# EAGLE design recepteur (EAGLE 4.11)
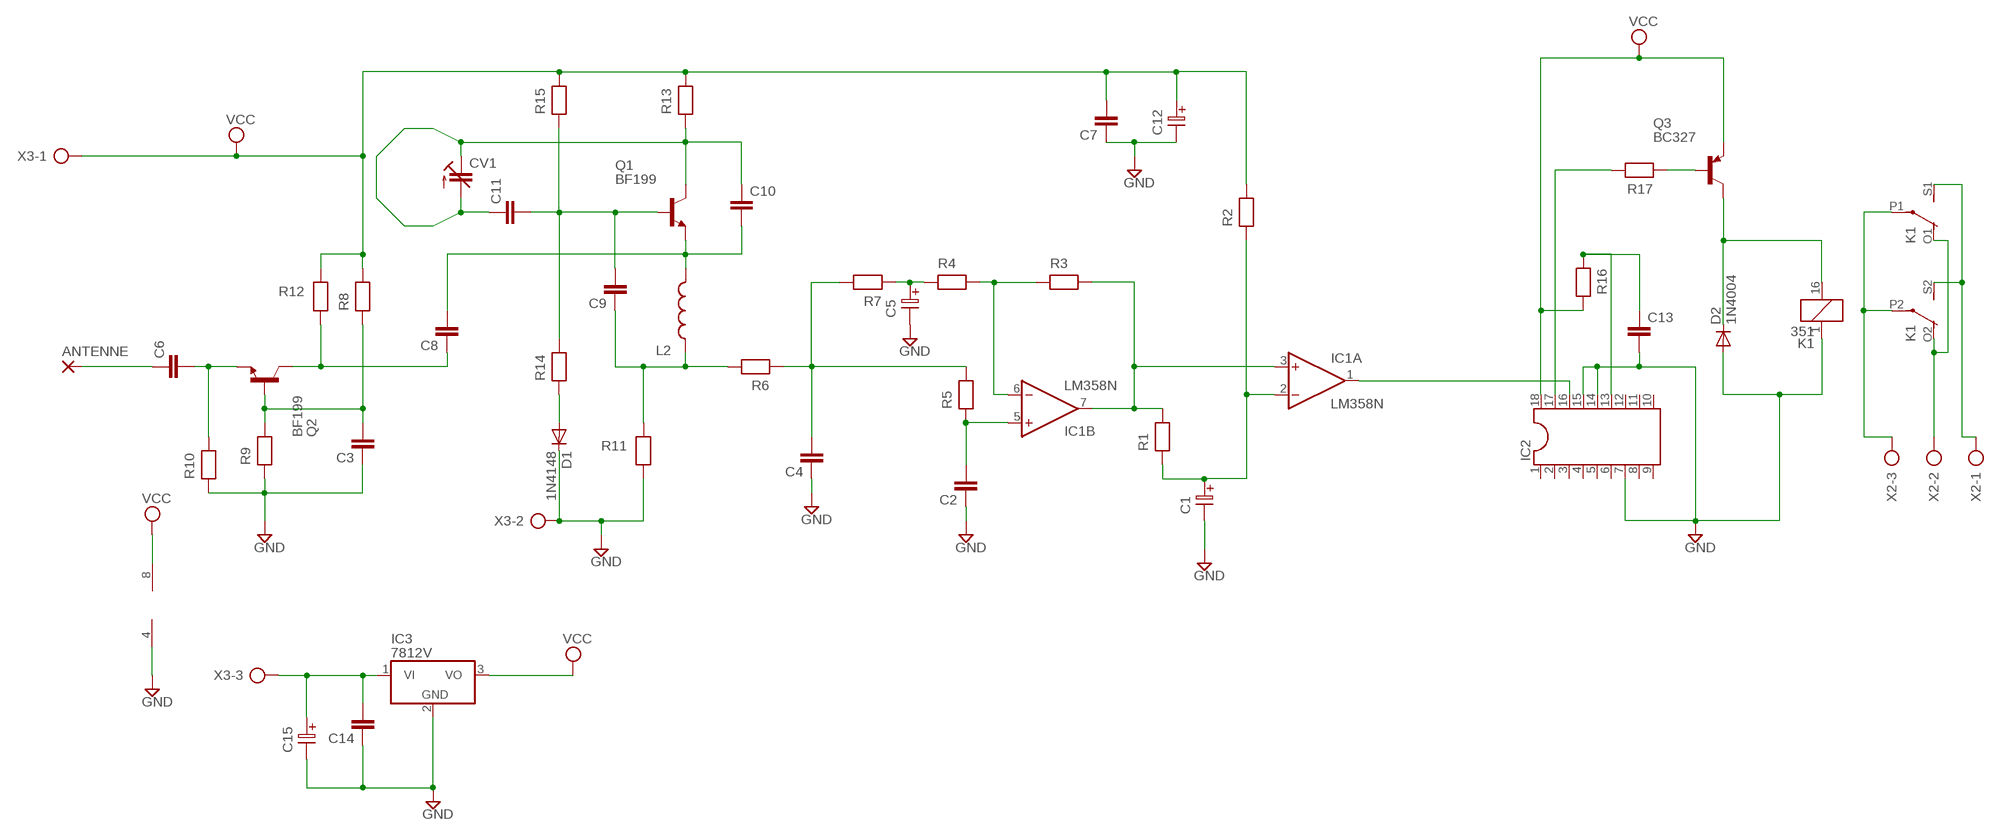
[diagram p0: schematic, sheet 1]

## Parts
ANTENNE  2,54/1,0  [2,54/1,0]
C1  ELC-5  [ES-5]
C2  C5/2.5  [C5B2.5]
C3  C5/2.5  [C5B2.5]
C4  C5/2.5  [C5B2.5]
C5  ELC-2,5L  [ES-2,5L]
C6  C5/2.5  [C5B2.5]
C7  C5/2.5  [C5B2.5]
C8  C5/2.5  [C5B2.5]
C9  C5/2.5  [C5B2.5]
C10  C5/2.5  [C5B2.5]
C11  C5/2.5  [C5B2.5]
C12  ELC-2,5L  [ES-2,5L]
C13  C5/2.5  [C5B2.5]
C14  C5/2.5  [C5B2.5]
C15  ELC-2,5L  [ES-2,5L]
CV1  C-TRIMM808  [CTRIM808-BC]
D1  1N4148  [DO35-10]
D2  1N4004  [DO41-10]
IC1  LM358N  [DIL08]
IC2  DIL18  [DIL18]
IC3  7812V  [TO220V]
K1  351  [351]
L2  L-7,5  [L-7,5]
Q1  BF199  [TO92]
Q2  BF199  [TO92]
Q3  BC327  [TO92]
R1  RESEU-12,5  [R-12,5]
R2  RESEU-12,5  [R-12,5]
R3  RESEU-12,5  [R-12,5]
R4  RESEU-12,5  [R-12,5]
R5  RESEU-S2,5  [RS-2,5]
R6  RESEU-12,5  [R-12,5]
R7  RESEU-S2,5  [RS-2,5]
R8  RESEU-12,5  [R-12,5]
R9  RESEU-12,5  [R-12,5]
R10  RESEU-S2,5  [RS-2,5]
R11  RESEU-S2,5  [RS-2,5]
R12  RESEU-S2,5  [RS-2,5]
R13  RESEU-S2,5  [RS-2,5]
R14  RESEU-12,5  [R-12,5]
R15  RESEU-12,5  [R-12,5]
R16  RESEU-12,5  [R-12,5]
R17  RESEU-12,5  [R-12,5]
X2  AK500/3  [AK500/3]
X3  AK500/3  [AK500/3]

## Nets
GND: C1.2 C2.1 C3.1 C4.1 C5.2 C7.1 C12.2 C13.2 C14.1 C15.2 D1.C D2.A IC1.4(P:V-) IC2.7 IC2.14 IC2.15 IC3.2(GND) K1.1 R9.1 R10.1 R11.2 X3.2
N$1: C9.1 L2.1 R6.2 R11.1
N$2: IC1.3(A:+IN) IC1.7(B:OUT) R1.2 R3.2
N$3: C1.1 IC1.2(A:-IN) R1.1 R2.1
N$4: C2.2 IC1.5(B:+IN) R5.1
N$5: C10.1 C11.1 CV1.1(E) CV1.2(A) Q1.3(C) R13.1
N$6: IC1.6(B:-IN) R3.1 R4.2
N$7: C5.1 R4.1 R7.1
N$8: C4.2 R5.2 R6.1 R7.2
N$9: K1.P1(2:P) K1.P2(3:P) X2.3
N$10: C3.2 Q2.1(B) R8.1 R9.2
N$11: C9.2 C11.2 Q1.1(B) R14.2 R15.1
N$12: C8.2 C10.2 L2.2 Q1.2(E)
N$13: D1.A R14.1
N$14: C6.2 Q2.2(E) R10.2
N$15: K1.O1(2:O) K1.O2(3:O) X2.2
N$16: C8.1 Q2.3(C) R12.2
N$18: C14.2 C15.1 IC3.1(VI) X3.3
N$19: ANTENNE.1(P) C6.1
N$20: D2.C K1.16 Q3.3(C)
N$21: IC1.1(A:OUT) IC2.16
N$22: C13.1 IC2.13 R16.1
N$23: K1.S1(2:S) K1.S2(3:S) X2.1
N$24: Q3.2(B) R17.1
N$25: IC2.17 R17.2
VCC: C7.2 C12.1 IC1.8(P:V+) IC2.18 IC3.3(VO) Q3.1(E) R2.2 R8.2 R12.1 R13.2 R15.2 R16.2 X3.1
Unconnected: IC2.1 IC2.2 IC2.3 IC2.4 IC2.5 IC2.6 IC2.8 IC2.9 IC2.10 IC2.11 IC2.12

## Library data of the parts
ANTENNE = wirepad:2,54/1,0: THROUGH-HOLE PAD
C1 = discrete:ELC-5
C2-C4 C6-C11 C13 C14 = capacitor-wima:C: CAPACITOR
C5 C12 C15 = discrete:ELC-2,5L
CV1 = rcl:C-TRIMM: Trimm capacitor
D1 = diode:1N4148: DIODE
D2 = diode:1N4004: DIODE
IC1 = linear:LM358: OP AMP
IC2 = ic-package:DIL18: Dual In Line
IC3 = linear:78*: Positive VOLTAGE REGULATOR
K1 = relay:351: RELAY 2 x switch, Omron
L2 = discrete:L-7,5
Q1 Q2 = transistor-npn:BF199*: NPN Transistor
Q3 = transistor-pnp:BC327: PNP Transistor
R1-R4 R6 R8 R9 R14-R17 = discrete:RESEU-12,5
R5 R7 R10-R13 = discrete:RESEU-S2,5
X2 X3 = con-ptr500:AK500/3: CONNECTOR

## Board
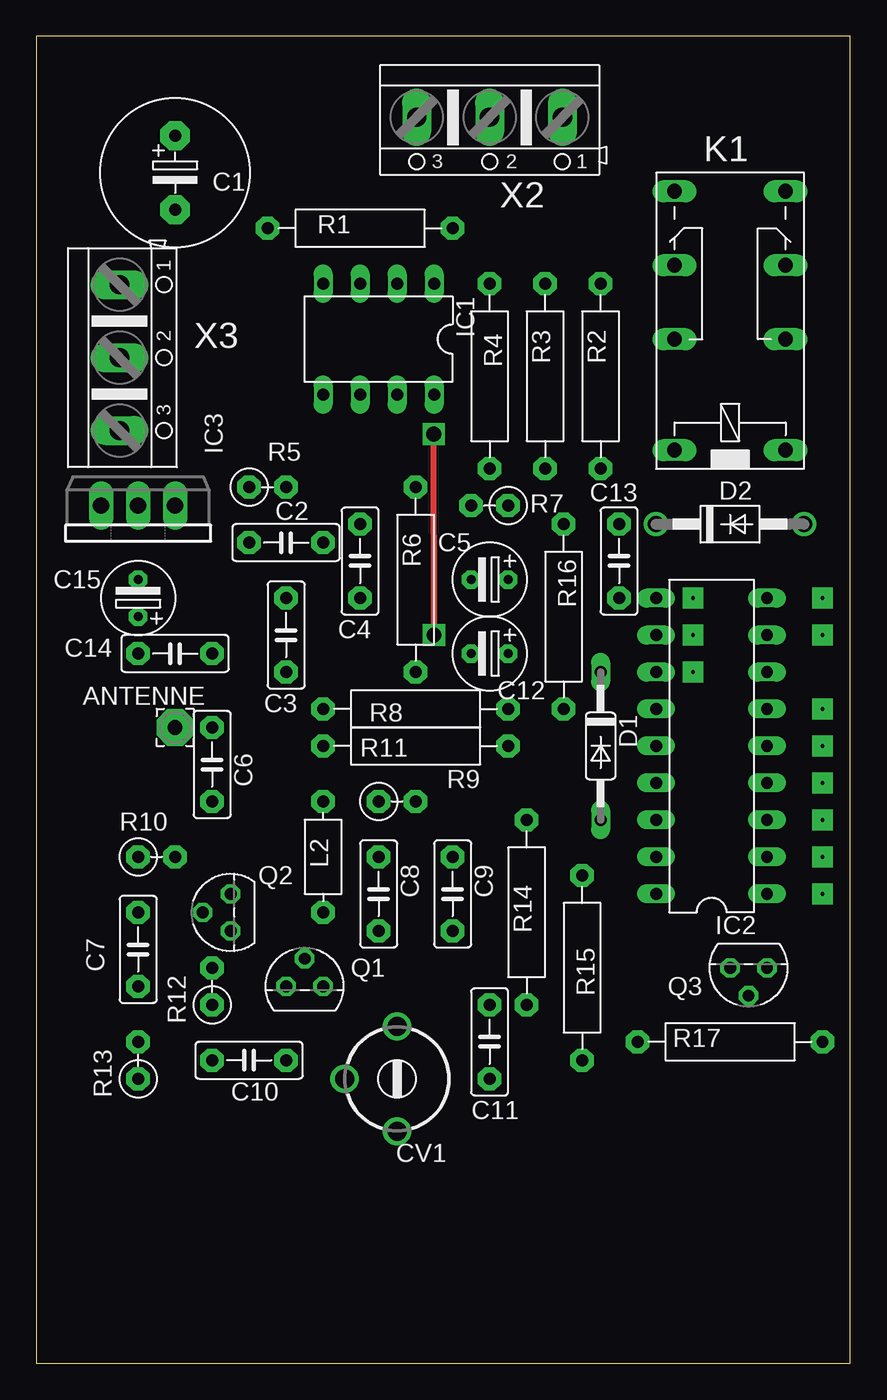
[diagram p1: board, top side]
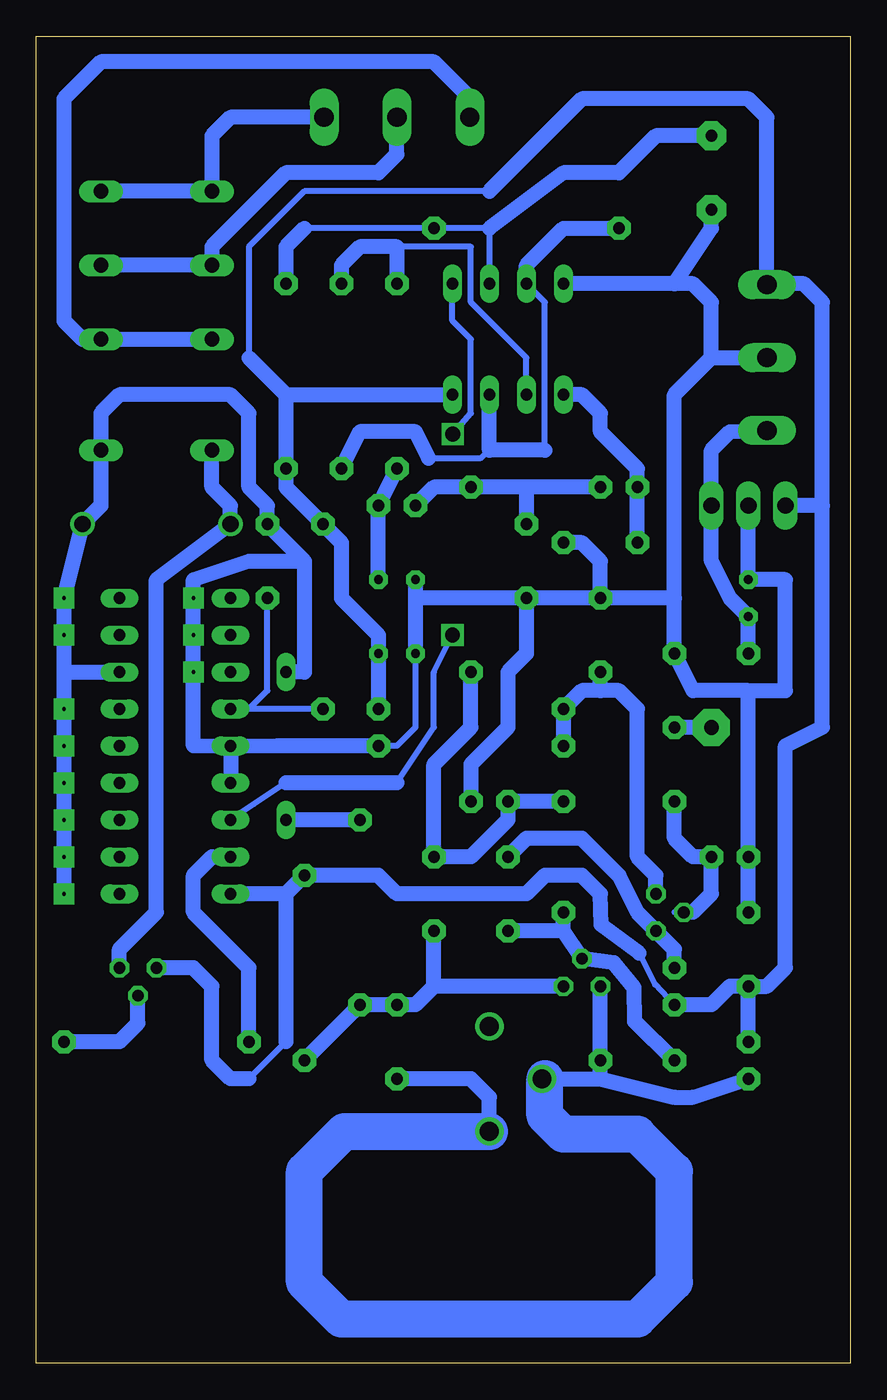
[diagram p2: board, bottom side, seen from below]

Size 55.86 x 91.11 mm. Coordinates in mm from the lower left corner, seen from the top.
Outline: 0,0 55.86,0 55.86,91.11 0,91.11 0,0
Copper layers 16: Bottom 0.035mm
Design rules "default": minimum track width 10mil, minimum drill 24mil, track to track 8mil, track to pad 8mil, pad to pad 8mil, via to via 8mil, smd to smd 8mil, copper to edge 40mil, drill to drill 8mil, minimum pad ring 10mil, minimum via ring 8mil, stop-mask expansion 4mil, vias tented up to drill 0mil, thermal gap 10mil

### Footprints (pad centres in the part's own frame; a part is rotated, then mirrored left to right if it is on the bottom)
2,54/1,0 = drill 1.016 pad 2.54 octagon: 1 0,0
ES-5 = drill 0.813 pad 2.007 octagon: 1 -2.54,0; 2 2.54,0
C5B2.5 = drill 0.813 pad 1.6 octagon: 1 -2.54,0; 2 2.54,0
ES-2,5L = drill 0.61 pad 1.27 octagon: 1 0,0; 2 2.54,0
CTRIM808-BC = drill 1.3 round: 1 -3.607,0; 2 0,3.607; 3 3.607,0
DO35-10 = drill 0.813 long: A 5.08,0; C -5.08,0
DO41-10 = drill 1.118 round: A 5.08,0; C -5.08,0
DIL08 = drill 0.813 long: 1 -3.81,-3.81; 2 -1.27,-3.81; 3 1.27,-3.81; 4 3.81,-3.81; 5 3.81,3.81; 6 1.27,3.81; 7 -1.27,3.81; 8 -3.81,3.81
DIL18 = drill 0.813 long: 1 -10.16,-3.81; 2 -7.62,-3.81; 3 -5.08,-3.81; 4 -2.54,-3.81; 5 0,-3.81; 6 2.54,-3.81; 7 5.08,-3.81; 8 7.62,-3.81; 9 10.16,-3.81; 10 10.16,3.81; 11 7.62,3.81; 12 5.08,3.81; 13 2.54,3.81; 14 0,3.81; 15 -2.54,3.81; 16 -5.08,3.81; 17 -7.62,3.81; 18 -10.16,3.81
TO220V = drill 1.118 long: 1 -2.54,-2.54; 2 0,-2.54; 3 2.54,-2.54
351 = drill 1.016 long: 1 -3.81,-3.81; 16 -3.81,3.81; O1 8.89,-3.81; O2 8.89,3.81; P1 3.81,-3.81; P2 3.81,3.81; S1 13.97,-3.81; S2 13.97,3.81
L-7,5 = drill 0.813 pad 1.6 octagon: 1 -3.81,0; 2 3.81,0
TO92 = drill 0.813 octagon: 1 1.27,0; 2 0,1.905; 3 -1.27,0
R-12,5 = drill 0.813 pad 1.6 octagon: 1 -6.35,0; 2 6.35,0
RS-2,5 = drill 0.813 pad 1.6 octagon: 1 0,0; 2 2.54,0
AK500/3 = drill 1.321 long: 1 -5.004,0; 2 0,0; 3 5.004,0

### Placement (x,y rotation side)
ANTENNE  9.52,43.65 0 top
C1  9.52,81.75 270 top
C2  17.14,56.35 180 top
C3  17.14,50 270 top
C4  22.22,55.08 90 top
C5  32.38,53.81 180 top
C6  12.06,41.11 270 top
C7  6.98,28.41 270 top
C8  23.49,32.22 270 top
C9  28.57,32.22 270 top
C10  14.6,20.79 180 top
C11  31.11,22.06 90 top
C12  32.38,48.73 180 top
C13  40,55.08 90 top
C14  9.52,48.73 180 top
C15  6.98,51.27 90 top
CV1  24.76,19.52 90 top
D1  38.73,42.38 270 top
D2  47.62,57.62 0 top
IC1  23.49,70.32 180 top
IC2  46.35,42.38 90 top
IC3  6.98,56.35 180 top
K1  47.62,66.51 90 top
L2  19.68,34.76 270 top
Q1  18.41,25.87 0 top
Q2  13.33,30.95 90 top
Q3  48.89,27.14 180 top
R1  22.22,77.94 180 top
R2  38.73,67.78 270 top
R3  34.92,67.78 270 top
R4  31.11,67.78 90 top
R5  14.6,60.16 0 top
R6  26.03,53.81 270 top
R7  32.38,58.89 180 top
R8  26.03,44.92 0 top
R9  26.03,42.38 180 top
R10  6.98,34.76 0 top
R11  23.49,38.57 0 top
R12  12.06,24.6 90 top
R13  6.98,19.52 90 top
R14  33.65,30.95 270 top
R15  37.46,27.14 90 top
R16  36.19,51.27 90 top
R17  47.62,22.06 180 top
X2  31.11,85.56 180 top
X3  5.71,69.05 270 top

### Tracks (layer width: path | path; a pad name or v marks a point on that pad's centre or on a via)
GND  (via drill 0.25 pad 1.42)
  Bottom 0.406: 29.84,52.54 C5.2 | 37.46,42.38 36.19,42.38 | C12.2 29.84,43.65 31.11,42.38 R9.1
  Bottom 1.016: C7.1 R10.1 6.98,46.19 | 6.98,46.19 10.79,46.19 C14.1 12.06,52.54 | 12.06,52.54 C3.1 | C3.1 17.14,55.08 18.41,56.35 C2.1 | C3.1 C4.1 | C4.1 29.84,52.54 | C5.2 C12.2 | R11.2 26.03,41.11 23.49,43.65 23.49,47.46 22.22,48.73 C4.1 | 12.06,74.13 IC1.4 | C1.2 9.52,77.94 12.06,74.13 | 37.46,55.08 C13.2 40,58.89 41.27,60.16 41.27,65.24 42.54,66.51 50.16,66.51 51.43,65.24 K1.1 51.43,58.89 D2.A v53.97,52.54 v53.97,50 53.97,47.46 | 37.46,55.08 41.27,55.08 45.08,53.81 v45.08,52.54 v45.08,50 v45.08,47.46 45.08,42.38 42.5,42.35 | D1.C 37.46,47.46 37.46,55.08 | 42.5,42.35 39.31,42.38 37.46,42.38 R9.1 | 9.52,69.05 9.52,72.86 10.79,74.13 12.06,74.13 | IC3.2 C15.2 4.44,53.81 4.44,46.19 6.98,46.19 | 9.52,69.05 12.06,66.51 12.06,52.54 | 9.52,69.05 X3.2 | 53.97,47.46 v53.97,44.92 v53.97,42.38 v53.97,39.84 v53.97,37.3 v53.97,34.76 v53.97,32.22 | 53.97,47.46 IC2.7 | 42.5,42.35 IC2.15 | 42.5,42.35 IC2.14
N$1
  Bottom 1.016: L2.1 R11.1 23.49,37.3 26.03,34.76 C9.1 28.57,41.11 26.03,43.65 R6.2
N$2
  Bottom 0.406: IC1.3 20.95,72.86 20.95,62.7 | 24.76,62.7 25.4,62.13 28.93,62.13
  Bottom 1.016: R1.2 19.68,77.94 22.22,75.4 IC1.3 | IC1.7 24.76,62.7 20.95,62.7 | R3.2 33.65,63.97 29.84,63.97 28.93,62.13
N$3
  Bottom 0.406: IC1.2 24.76,77.94 R1.1 37.46,77.94
  Bottom 1.016: C1.1 13.33,84.29 15.87,81.75 19.68,81.75 24.76,77.94 | R2.1 38.73,76.67 37.46,77.94
N$4
  Bottom 1.016: C2.2 R5.1 14.6,61.43 17.14,63.97 17.14,65.24 18.41,66.51 IC1.5
N$5
  Bottom 0.406: 20.95,19.52 CV1.2 | CV1.1 24.76,15.71
  Bottom 1.016: C11.1 26.03,19.52 24.76,18.25 CV1.1 | 17.14,19.52 12.06,18.25 10.79,18.25 R13.1 | Q1.3 C10.1 17.14,19.52 | 20.95,19.52 17.14,19.52
  Bottom 2.54: CV1.1 34.72,15.91 37.46,13.17 37.46,5.55 34.92,3.01 14.6,3.01 12.06,5.55 12.06,13.17 14.6,15.71 19.68,15.71 20.95,16.98 20.95,19.52
N$6
  Bottom 0.406: IC1.6 22.22,69.05 26.03,72.86 26.03,76.67 31.11,76.67
  Bottom 1.016: R3.1 34.92,75.4 33.65,76.67 31.11,76.67 R4.2
N$7
  Bottom 1.016: C5.1 R7.1 R4.1
N$8
  Bottom 1.016: R5.2 22.22,60.16 | 22.22,60.16 C4.2 | 22.22,60.16 R6.1 28.57,60.16 R7.2
N$9
  Bottom 0.406: 52.7,70.32 K1.P1
  Bottom 1.016: K1.P1 K1.P2 | 52.7,70.32 53.97,71.59 53.97,86.83 51.43,89.37 28.57,89.37 26.11,86.91 X2.3
N$10
  Bottom 1.016: Q2.1 13.33,33.49 14.6,34.76 14.6,44.92 15.87,46.19 17.14,46.19 | 17.14,46.19 18.41,46.19 R8.1 R9.2 | 17.14,46.19 C3.2
N$11
  Bottom 1.016: 28.57,25.87 29.84,24.6 C11.2 R14.2 R15.1 | 28.57,25.87 C9.2 | Q1.1 28.57,25.87
N$12
  Bottom 1.016: 19.68,29.68 L2.2 | 19.68,29.68 C8.2 | 19.68,29.68 Q1.2 16.22,27.5 14.83,25.77 14.79,23.45 C10.2
N$13
  Bottom 1.016: R14.1 D1.A
N$14
  Bottom 0.406: Q2.2 12.06,30.95
  Bottom 1.016: C6.2 12.06,36.03 10.79,34.76 R10.2 9.52,32.22 10.79,30.95 Q2.2
N$15
  Bottom 1.016: K1.O1 K1.O2 43.81,76.67 38.73,81.75 32.38,81.75 31.11,83.02 X2.2
N$16
  Bottom 1.016: R12.2 12.06,28.41 Q2.3 14.6,30.95 15.87,33.49 18.41,36.03 22.22,36.03 C8.1
N$18
  Bottom 1.016: C14.2 C15.1 8.25,52.54 9.52,55.08 IC3.1 9.52,62.7 8.25,63.97 X3.3
N$19
  Bottom 1.016: ANTENNE.1 C6.1
N$20
  Bottom 1.016: Q3.3 50.16,28.41 47.62,30.95 47.62,53.81 D2.C 42.54,58.89 43.81,60.16 K1.16
N$21  (via drill 1.02)
  Top 0.406: v27.3,50 v27.28,63.81 v27.3,50
  Bottom 0.406: IC2.16 40.96,38.37 38.73,39.84 | 31.11,39.84 28.57,43.65 28.57,47.46 v27.3,50 | IC1.1 27.3,71.59 26.03,70.32 26.03,65.24 v27.28,63.81
  Bottom 1.016: 31.11,39.84 38.73,39.84
N$22
  Bottom 0.406: C13.1 40,46.19 41.27,44.92 IC2.13 R16.1
N$23
  Bottom 1.016: X2.1 42.54,85.56 43.81,84.29 K1.S2 K1.S1
N$24
  Bottom 1.016: Q3.2 48.89,23.33 50.16,22.06 R17.1
N$25
  Bottom 1.016: IC2.17 43.81,34.76 45.08,33.49 45.08,30.95 41.27,27.14 R17.2
VCC
  Bottom 0.406: 38.73,22.06 41.27,19.52 | 24.76,80.48 37.46,80.48 41.27,76.67 41.27,69.05 | 5.71,74.13 X3.1 | R12.1 13.38,26 14.48,28.15
  Bottom 1.016: R13.2 C7.2 | 38.73,32.22 IC2.18 | Q3.1 45.08,27.14 43.81,25.87 43.81,20.79 42.54,19.52 41.27,19.52 | 38.73,32.22 R15.2 32.38,33.49 31.11,32.22 22.22,32.22 20.95,33.49 18.41,33.49 17.14,32.22 17.09,30.1 14.48,28.15 | 38.73,32.22 38.73,22.06 | R8.2 C12.1 32.38,50 34.92,52.54 34.92,56.35 R16.2 38.73,60.16 R2.2 38.73,66.51 | 24.76,80.48 18.41,86.83 6.98,86.83 5.71,85.56 5.71,74.13 3.17,74.13 1.9,72.86 1.9,58.89 | 41.27,69.05 38.73,66.51 | 38.73,66.51 IC1.8 | R12.1 9.52,24.6 8.25,25.87 C7.2 | C7.2 5.71,25.87 4.44,27.14 4.44,42.38 1.9,43.65 1.9,58.89 | 1.9,58.89 IC3.3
